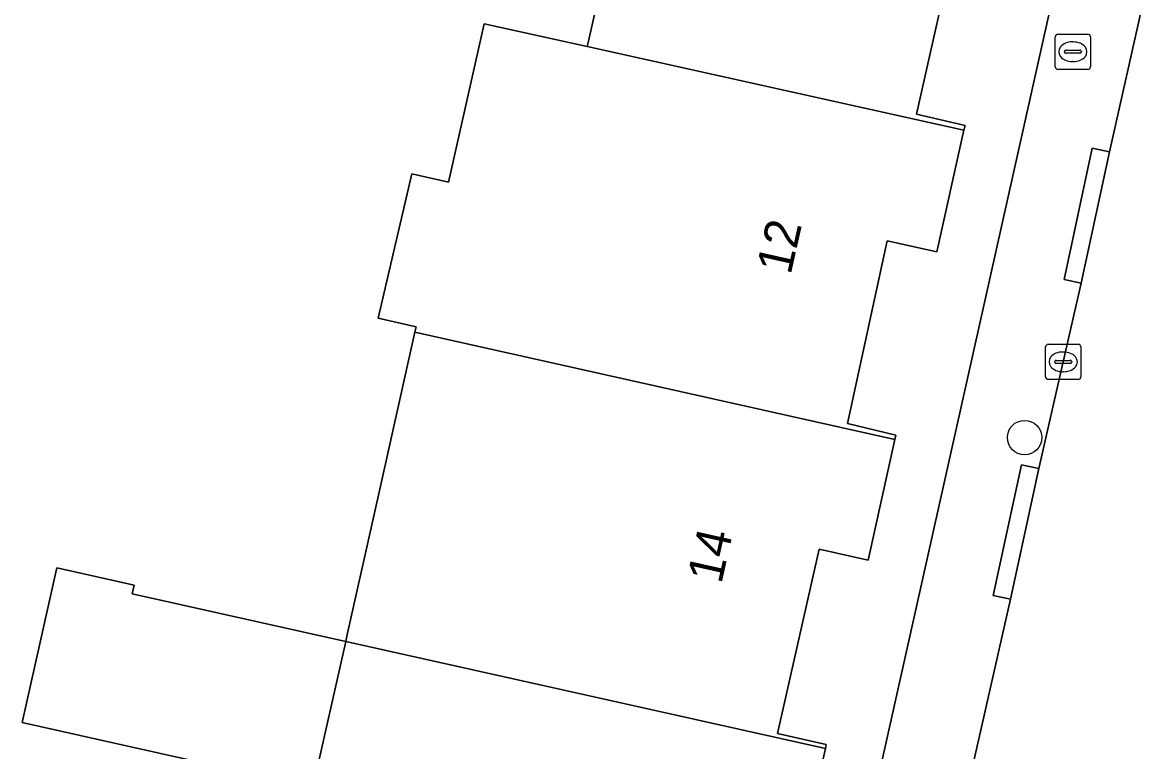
# Model space of a CAD drawing. Extents: x 161771 to 163125, y 382475 to 383179.
# Drawn here: x 162599.42 to 162630.99, y 382604.09 to 382624.81 of the extents above; entities that cross this region are included whole.
import ezdxf

# ---------------------------------------------------------------- set-up
doc = ezdxf.new("R2010")
doc.units = 0
for name, color, linetype in [('IMGEO_Boom', 7, 'Continuous'), ('IMGEO_Brandkraan', 7, 'Continuous'), ('IMGEO_Erf', 7, 'Continuous'), ('IMGEO_Kolk', 7, 'Continuous'), ('IMGEO_Pand', 7, 'Continuous'), ('IMGEO_Pand_nummerreeks', 7, 'Continuous'), ('IMGEO_Rijbaan_lokaal_open', 7, 'Continuous'), ('IMGEO_Voetpad_open', 7, 'Continuous')]:
    doc.layers.add(name, color=color, linetype=linetype)

msp = doc.modelspace()

# ---------------------------------------------------------------- linework, layer by layer
at = {"layer": 'IMGEO_Boom'}
msp.add_circle((162627.889, 382613.011), 0.489, dxfattribs=at)
at = {"layer": 'IMGEO_Brandkraan'}
for p, q in [((162628.76, 382623.542), (162628.76, 382624.394)), ((162628.835, 382624.468), (162629.687, 382624.468)), ((162629.761, 382624.394), (162629.761, 382623.542)), ((162629.248, 382624.248), (162629.273, 382624.248)), ((162629.019, 382623.962), (162629.019, 382623.974)), ((162629.457, 382623.925), (162629.059, 382623.925)), ((162629.062, 382624.011), (162629.46, 382624.011)), ((162629.503, 382623.974), (162629.503, 382623.962)), ((162629.687, 382623.468), (162628.835, 382623.468)), ((162629.271, 382623.688), (162629.246, 382623.688))]:
    msp.add_line(p, q, dxfattribs=at)
for points in [[(162628.76, 382623.542), (162628.76, 382624.394)], [(162628.835, 382624.468), (162629.687, 382624.468)], [(162629.761, 382624.394), (162629.761, 382623.542)], [(162629.687, 382623.468), (162628.835, 382623.468)]]:
    msp.add_lwpolyline(points, dxfattribs=at)
for centre, radius, start, end in [((162628.837, 382624.392), 0.0765, 91.552, 178.448), ((162628.837, 382624.392), 0.0765, 91.552, 178.448), ((162629.685, 382624.392), 0.0765, 1.552, 88.448), ((162629.685, 382624.392), 0.0765, 1.552, 88.448), ((162629.059, 382623.971), 0.0403, 85.8775, 175.7526), ((162629.056, 382623.961), 0.0366, 178.938, 274.7102), ((162629.46, 382623.968), 0.043, 264.8664, 352.4533), ((162629.464, 382623.973), 0.0386, 1.7309, 96.639), ((162628.837, 382623.544), 0.0765, 181.552, 268.448), ((162628.837, 382623.544), 0.0765, 181.552, 268.448), ((162629.685, 382623.544), 0.0765, 271.552, 358.448), ((162629.685, 382623.544), 0.0765, 271.552, 358.448)]:
    msp.add_arc(centre, radius, start, end, dxfattribs=at)
for centre, major_axis, ratio, start_param, end_param in [((162629.247, 382623.968), (-0.387, 0.002), 0.722429, 4.712389, 7.853982), ((162629.272, 382623.968), (-0.39, 0.002), 0.717154, 1.570796, 4.712389)]:
    msp.add_ellipse(centre, major_axis=major_axis, ratio=ratio, start_param=start_param, end_param=end_param, dxfattribs=at)
at = {"layer": 'IMGEO_Erf'}
for points in [[(162621.402, 382592.881), (162622.207, 382596.532), (162640.083, 382676.445)], [(162607.674, 382603.072), (162601.611, 382604.432), (162599.415, 382604.924), (162600.4, 382609.315), (162602.596, 382608.823), (162602.54, 382608.574), (162608.603, 382607.222), (162608.636, 382607.369), (162609.553, 382611.458), (162610.571, 382616.002), (162610.607, 382616.161), (162609.526, 382616.402), (162610.48, 382620.503), (162611.527, 382620.269), (162612.535, 382624.763), (162615.464, 382624.113), (162615.499, 382624.268), (162616.426, 382628.405)], [(162625.983, 382627.376), (162624.82, 382622.196), (162626.197, 382621.876), (162626.166, 382621.738), (162625.392, 382618.288), (162623.99, 382618.594), (162622.859, 382613.414), (162624.233, 382613.083), (162624.205, 382612.958), (162623.441, 382609.534), (162622.056, 382609.847), (162620.871, 382604.61), (162622.256, 382604.296), (162622.231, 382604.183), (162621.454, 382600.75)]]:
    msp.add_lwpolyline(points, dxfattribs=at)
at = {"layer": 'IMGEO_Kolk'}
for p, q in [((162628.486, 382614.736), (162628.486, 382615.588)), ((162628.561, 382615.662), (162629.413, 382615.662)), ((162629.487, 382615.588), (162629.487, 382614.736)), ((162628.974, 382615.442), (162628.999, 382615.442)), ((162628.745, 382615.156), (162628.745, 382615.168)), ((162629.183, 382615.119), (162628.785, 382615.119)), ((162628.788, 382615.205), (162629.186, 382615.205)), ((162629.229, 382615.168), (162629.229, 382615.156)), ((162629.413, 382614.662), (162628.561, 382614.662)), ((162628.997, 382614.882), (162628.972, 382614.882))]:
    msp.add_line(p, q, dxfattribs=at)
for points in [[(162628.486, 382614.736), (162628.486, 382615.588)], [(162628.561, 382615.662), (162629.413, 382615.662)], [(162629.487, 382615.588), (162629.487, 382614.736)], [(162629.413, 382614.662), (162628.561, 382614.662)]]:
    msp.add_lwpolyline(points, dxfattribs=at)
for centre, radius, start, end in [((162628.563, 382615.586), 0.0765, 91.552, 178.448), ((162628.563, 382615.586), 0.0765, 91.552, 178.448), ((162629.411, 382615.586), 0.0765, 1.552, 88.448), ((162629.411, 382615.586), 0.0765, 1.552, 88.448), ((162628.785, 382615.165), 0.0403, 85.8775, 175.7526), ((162628.782, 382615.155), 0.0366, 178.938, 274.7102), ((162629.186, 382615.162), 0.043, 264.8664, 352.4533), ((162629.19, 382615.167), 0.0386, 1.7309, 96.639), ((162628.563, 382614.738), 0.0765, 181.552, 268.448), ((162628.563, 382614.738), 0.0765, 181.552, 268.448), ((162629.411, 382614.738), 0.0765, 271.552, 358.448), ((162629.411, 382614.738), 0.0765, 271.552, 358.448)]:
    msp.add_arc(centre, radius, start, end, dxfattribs=at)
for centre, major_axis, ratio, start_param, end_param in [((162628.973, 382615.162), (-0.387, 0.002), 0.722429, 4.712389, 7.853982), ((162628.998, 382615.162), (-0.39, 0.002), 0.717154, 1.570796, 4.712389)]:
    msp.add_ellipse(centre, major_axis=major_axis, ratio=ratio, start_param=start_param, end_param=end_param, dxfattribs=at)
at = {"layer": 'IMGEO_Pand'}
for points in [[(162625.983, 382627.376), (162627.363, 382627.066), (162628.128, 382630.514), (162617.431, 382632.893), (162614.502, 382633.544), (162613.498, 382629.061), (162616.426, 382628.405), (162615.499, 382624.268), (162615.464, 382624.113), (162626.166, 382621.738), (162626.197, 382621.876), (162624.82, 382622.196)], [(162623.99, 382618.594), (162625.392, 382618.288), (162626.166, 382621.738), (162615.464, 382624.113), (162612.535, 382624.763), (162611.527, 382620.269), (162610.48, 382620.503), (162609.526, 382616.402), (162610.607, 382616.161), (162610.571, 382616.002), (162624.205, 382612.958), (162624.233, 382613.083), (162622.859, 382613.414)], [(162622.056, 382609.847), (162623.441, 382609.534), (162624.205, 382612.958), (162610.571, 382616.002), (162609.553, 382611.458), (162608.636, 382607.369), (162608.603, 382607.222), (162622.231, 382604.183), (162622.256, 382604.296), (162620.871, 382604.61)], [(162608.603, 382607.222), (162602.54, 382608.574), (162602.596, 382608.823), (162600.4, 382609.315), (162599.415, 382604.924), (162601.611, 382604.432), (162607.674, 382603.072)], [(162622.231, 382604.183), (162608.603, 382607.222), (162607.674, 382603.072), (162607.589, 382602.695), (162610.517, 382602.039), (162609.511, 382597.549), (162618.835, 382595.504), (162620.096, 382601.054), (162621.454, 382600.75)]]:
    msp.add_lwpolyline(points, close=True, dxfattribs=at)
at = {"layer": 'IMGEO_Rijbaan_lokaal_open'}
msp.add_lwpolyline([(162631.396, 382626.021), (162630.297, 382621.123), (162629.498, 382617.399), (162628.987, 382615.158), (162628.293, 382612.132), (162627.486, 382608.423), (162626.379, 382603.537), (162625.55, 382599.824), (162624.721, 382596.089), (162629.852, 382595.048), (162629.327, 382592.855)], dxfattribs=at)
at = {"layer": 'IMGEO_Voetpad_open'}
for points in [[(162643.112, 382689.963), (162641.523, 382682.919), (162640.083, 382676.445), (162622.207, 382596.532), (162621.402, 382592.881)], [(162623.768, 382594.099), (162624.258, 382594), (162624.721, 382596.089), (162625.55, 382599.824), (162625.063, 382599.932), (162625.892, 382603.645), (162626.379, 382603.537), (162627.486, 382608.423), (162626.998, 382608.529), (162627.805, 382612.238), (162628.293, 382612.132), (162628.987, 382615.158), (162629.498, 382617.399), (162629.01, 382617.503), (162629.809, 382621.227), (162630.297, 382621.123), (162631.396, 382626.021)]]:
    msp.add_lwpolyline(points, dxfattribs=at)
for points in [[(162630.297, 382621.123), (162629.809, 382621.227), (162629.01, 382617.503), (162629.498, 382617.399)], [(162627.486, 382608.423), (162628.293, 382612.132), (162627.805, 382612.238), (162626.998, 382608.529)]]:
    msp.add_lwpolyline(points, close=True, dxfattribs=at)

# ---------------------------------------------------------------- texts
at = {"layer": 'IMGEO_Pand_nummerreeks'}
for s, p in [('12', (162621.242, 382617.611)), ('14', (162619.274, 382608.832))]:
    msp.add_text(s, height=1, rotation=77.3665, dxfattribs=at).set_placement(p)

doc.saveas('drawing.dxf')
